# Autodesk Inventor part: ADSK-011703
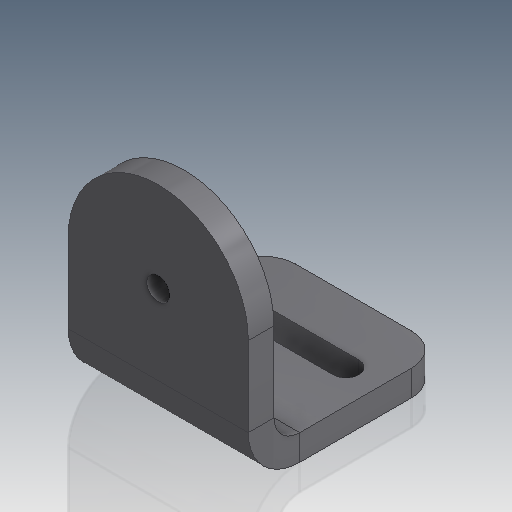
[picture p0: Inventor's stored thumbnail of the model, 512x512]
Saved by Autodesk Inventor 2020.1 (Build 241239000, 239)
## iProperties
Created: 2000-03
Part Number: ADSK-011703
Material: 1.0312 DC05
Document SubType Name: Tôlerie
Designer: cmcgourin
Density: 1 g/cm^3
Sheet Metal Rule: Stahlblech 1.0312 - DC05 -  10.0 mm
Appearance: Metal-Steel(Polish)
Mass: 90.1434 g
Surface Area: 234.091 cm^2
Volume: 90.1434 cm^3
Sheet Metal Width: 70,000 mm
Sheet Metal Length: 144,619 mm
Sheet Metal Area: 10123,363 mm^2
Flat Pattern Width: 7 cm
Flat Pattern Length: 14.4619 cm
Flat Pattern Area: 101.234 cm^2
Control State: 0
Master: False
Checked Out: False
Shininess: 25.0
Length Units: 11269
Angle Units: 11279
Time Units: 11290
Mass Units: 11283
Length Display Precision: 3
Angle Display Precision: 2
Compacted: True
Cutlength: 23.25
Material Desc: Material Description goes here
Material_Number: Pearson
G_L: 70x144,6 mm
Thickness: 10,000 mm
Dimensions: 86x76x70 mm
Mass: 0,09 kg
Semi finished: Stahlblech 1.0312 - DC05 -  10.0 mm
DocNumber: ADSK-011703.ipt
Folder: 01 - Themengebiete\Simplification\01 - Packaging machine\
VDS_Category: 3D Komponenten
VLT_Material: 1.0312 DC05
Density: 0.0
Volumn: 0.0
Area: 0.0
PropertySet Name: Model Information
Author: cmcgourin
Revision Number: -
Title: angle
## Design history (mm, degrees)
node "Solide1"
  node "Konturlasche1"
workplane "Arbeitsebene3"
feature "Biegung2" dims "d40" = 10 (= Thickness), "d42" = 10 (= BendReliefWidth), "d43" = 5 (= BendReliefDepth), "d44" = 20 (= MinimumRemnant), "d45" = 10 (= TransitionRadius), "d47" = 10 (= BendRadius), "d48" = 10, "SeamGap" = 0.00508
feature "Ecke1" dims "d48" = 10, "d49" = 40 (= CornerReliefSize), "d50" = 10 (= TailleJeu), "d51" = 10 (= TailleRayonJacobi)
feature "Eckenrundung3" dims "d52" = 35 (= 0.5 x d46), "d65" = 12.5
sketch "Skizze7"
  geometry: A1 r 35 centre (35, 31) between (70, 31) and (0, 31) reference; 2 further points
  constraints: 1 coincident
hole "Bohrung2" sketch "Skizze7" diameter "d53" = 9; stored, may be unused: countersink angle "d57" = 90 deg, drill point angle "d59" = 118 deg; dims "d54" = 16, "d55" = 20, "d56" = 2, "d58" = 10 (= Thickness)
sketch "Skizze8"
  geometry: L1 (57, -25)-(13, -25); L2 (57, -30)-(13, -30); L3 (13, -20)-(57, -20); L4 (70, -76)-(0, -76) reference; L5 (0, 0)-(70, 0) reference; A1 r 5 centre (57, -25) between (57, -30) and (57, -20); A2 r 5 centre (13, -25) between (13, -20) and (13, -30); 3 further points
  constraints: 8 end point, 4 point on circle, 4 tangent, 2 centre point, 2 midpoint, 1 horizontal, 1 parallel, 1 vertical alignment
  dimensions: "d60" = 10 distance between parallel lines of L2 L3; "d61" = 44 distance of L3.start L3.end; "d62" = 25 distance between parallel lines of L5 L1
feature "Ausklinkung1" dims "d63" = 10 (= Thickness), "d64" = 0
sketch "Sketch3"
  geometry: L1 (86, 0)-(0, 0); L2 (0, 0)-(0, -76); 1 further point
  constraints: 4 end point, 1 coincident, 1 horizontal, 1 perpendicular
  dimensions: "d11" = 76 distance of L1.end L2.end; "d41" = 86 distance of L1.start L1.end
feature "Grobblech3" dims "d40" = 10 (= Thickness), "d42" = 10 (= BendReliefWidth), "d43" = 5 (= BendReliefDepth), "d44" = 20 (= MinimumRemnant), "d45" = 10 (= TransitionRadius), "d46" = 70, "d47" = 10 (= BendRadius), "d48" = 10, "d49" = 40 (= CornerReliefSize), "d50" = 10 (= TailleJeu), "d51" = 10 (= TailleRayonJacobi), "SeamGap" = 0.00508
node "Corps solides"
node "Corps surfaciques"
feature "Definition1"
other parameters: "Vertical_Length" = 63.5, "Horizontal_length" = 38.1, "Thickness" = 10 (derived), "BendRadius" = 10 (= Thickness), "BendReliefDepth" = 5 (= 0.5 x Thickness), "BendReliefDepth" = 5, "Horizontal_length" = 38.1, "Thickness" = 10, "Vertical_Length" = 63.5
